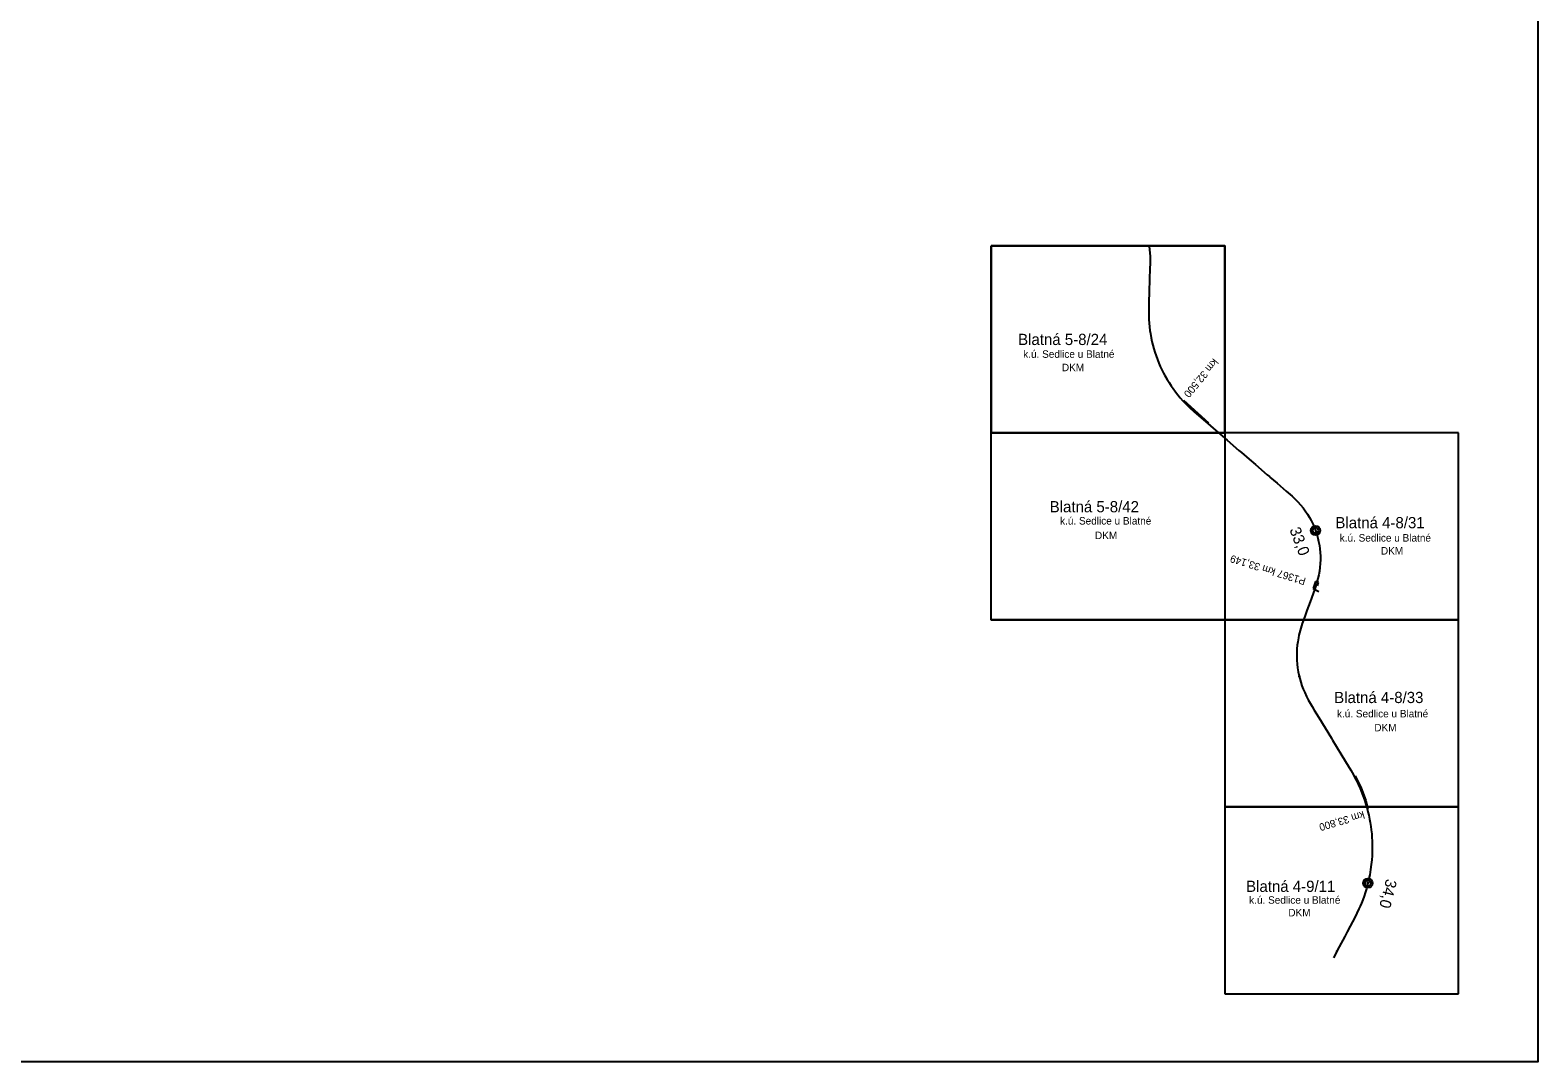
# Model space of a CAD drawing. Extents: x -793522 to -786663, y -1118682 to -1109366.
# Drawn here: x -790694 to -786663, y -1118682 to -1115923 of the extents above; entities that cross this region are included whole.
import ezdxf

# ---------------------------------------------------------------- set-up
doc = ezdxf.new("R2010")
doc.units = 0
doc.layers.add('Vrstva 1', color=7, linetype='Continuous')
doc.layers.add('Vrstva 5', color=7, linetype='Continuous')

msp = doc.modelspace()

# ---------------------------------------------------------------- linework, layer by layer
at = {"layer": 'Vrstva 1'}
for p, q in [((-787500, -1116500), (-788125, -1116500)), ((-788125, -1116500), (-788125, -1117000)), ((-787500, -1117000), (-787500, -1116500)), ((-787610.17, -1116912.47), (-787543.59, -1116973.16)), ((-788125, -1117000), (-787500, -1117000)), ((-786875, -1117000), (-787500, -1117000)), ((-787500, -1117000), (-787500, -1117500)), ((-786875, -1117500), (-786875, -1117000)), ((-787257.92, -1117397.49), (-787263.58, -1117416.4)), ((-787263.58, -1117416.4), (-787248.8, -1117423.73)), ((-787249.76, -1117400.11), (-787257.92, -1117397.49)), ((-787252.28, -1117409.05), (-787249.76, -1117400.11)), ((-788125, -1117500), (-787500, -1117500)), ((-786875, -1117500), (-787500, -1117500)), ((-787500, -1117500), (-787500, -1118000)), ((-787500, -1117500), (-786875, -1117500)), ((-786875, -1118000), (-786875, -1117500)), ((-787151.77, -1117917.42), (-787135.79, -1117950.31)), ((-787135.79, -1117950.31), (-787123.32, -1117983.19)), ((-787123.32, -1117983.19), (-787117.52, -1118004.28)), ((-786875, -1118000), (-787500, -1118000)), ((-787500, -1118000), (-787500, -1118500)), ((-787500, -1118000), (-786875, -1118000)), ((-786875, -1118500), (-786875, -1118000)), ((-787500, -1118500), (-786875, -1118500))]:
    msp.add_line(p, q, dxfattribs=at)
for points in [[(-788125, -1116500), (-787500, -1116500), (-787500, -1117000), (-788125, -1117000)], [(-788125, -1117000), (-787500, -1117000), (-787500, -1117500), (-788125, -1117500)]]:
    msp.add_lwpolyline(points, close=True, dxfattribs=at)
at = {"layer": 'Vrstva 5'}
msp.add_line((-787264.124, -1117429.531), (-787272.215, -1117452.199), dxfattribs=at)
msp.add_lwpolyline([(-793521.92, -1109366.5), (-786663.17, -1109366.5), (-786663.17, -1118682.04), (-793521.92, -1118682.04)], close=True, dxfattribs=at)
for points in [[(-787702.18, -1116501.519), (-787700.372, -1116518.851), (-787699.928, -1116528.643), (-787699.805, -1116538.532), (-787699.903, -1116548.479), (-787700.14, -1116558.804)], [(-787700.14, -1116558.804), (-787701.094, -1116590.796), (-787701.939, -1116620.528), (-787702.796, -1116651.973)], [(-787702.796, -1116651.973), (-787702.839, -1116653.476), (-787703.182, -1116666.814), (-787703.224, -1116669.056), (-787703.262, -1116685.938), (-787702.875, -1116697.001), (-787702.251, -1116706.456), (-787701.319, -1116716.327), (-787700.066, -1116726.364), (-787698.933, -1116733.965), (-787696.768, -1116746.104), (-787694.788, -1116755.499), (-787692.394, -1116765.447), (-787689.88, -1116774.799), (-787687.019, -1116784.337), (-787683.839, -1116793.908), (-787680.302, -1116803.582), (-787676.467, -1116813.13), (-787672.577, -1116822.084), (-787668.102, -1116831.643), (-787663.922, -1116839.942), (-787660.465, -1116846.442), (-787654.268, -1116857.303), (-787649.157, -1116865.615), (-787643.467, -1116874.28), (-787638.382, -1116881.6), (-787631.784, -1116890.547), (-787626.005, -1116897.887), (-787619.293, -1116905.951), (-787612.03, -1116914.141), (-787605.82, -1116920.753), (-787594.635, -1116931.834), (-787581.88, -1116943.427), (-787568.993, -1116954.583)], [(-787568.993, -1116954.583), (-787545.215, -1116975.067), (-787531.212, -1116987.128), (-787493.359, -1117019.729), (-787462.151, -1117046.641), (-787455.433, -1117052.443), (-787434.547, -1117070.453)], [(-787434.547, -1117070.453), (-787417.79, -1117084.905), (-787386.337, -1117112.07), (-787380.687, -1117116.941), (-787379.218, -1117118.208), (-787360.32, -1117134.512), (-787335.866, -1117155.607)], [(-787335.866, -1117155.607), (-787320.244, -1117169.319), (-787311.1, -1117177.883), (-787305.041, -1117183.968)], [(-787305.041, -1117183.968), (-787297.251, -1117192.53), (-787290.607, -1117200.614), (-787284.884, -1117208.27), (-787278.988, -1117216.979), (-787273.485, -1117226.042), (-787269.093, -1117234.068), (-787264.497, -1117243.474), (-787260.627, -1117252.403), (-787257.299, -1117261.108), (-787254.006, -1117271.02), (-787251.155, -1117281.268), (-787249.101, -1117290.263), (-787247.167, -1117300.814), (-787245.916, -1117309.872), (-787244.976, -1117319.945), (-787244.497, -1117329.869), (-787244.472, -1117339.844), (-787244.881, -1117349.453), (-787245.815, -1117359.915), (-787247.114, -1117369.403), (-787249.025, -1117379.864), (-787251.285, -1117389.688)], [(-787251.285, -1117389.688), (-787253.839, -1117398.971), (-787255.092, -1117403.108), (-787257.722, -1117411.266), (-787259.626, -1117416.843), (-787264.124, -1117429.531)], [(-787272.215, -1117452.199), (-787280.557, -1117475.364), (-787286.198, -1117490.977), (-787292.861, -1117509.706)], [(-787292.861, -1117509.706), (-787298.773, -1117528.625), (-787301.815, -1117540.929), (-787303.306, -1117548.175), (-787305.082, -1117558.822), (-787306.246, -1117568.012), (-787307.096, -1117577.718), (-787307.561, -1117587.67), (-787307.605, -1117599.168), (-787307.529, -1117601.826), (-787307.284, -1117607.901), (-787306.437, -1117618.657), (-787305.227, -1117628.663), (-787303.498, -1117639.154), (-787301.836, -1117647.306), (-787299.475, -1117657.058), (-787296.766, -1117666.621), (-787293.658, -1117676.109), (-787290.249, -1117685.268), (-787286.351, -1117694.595), (-787281.343, -1117705.236), (-787276.745, -1117714.024), (-787271.82, -1117722.762), (-787266.305, -1117732.107), (-787260.785, -1117741.263), (-787248.978, -1117760.785), (-787231.984, -1117788.82), (-787215.165, -1117816.515), (-787212.016, -1117821.729), (-787202.567, -1117837.346), (-787187.195, -1117862.716), (-787170.659, -1117890.037), (-787163.422, -1117902.053), (-787156.387, -1117914.217), (-787154.007, -1117918.544), (-787148.709, -1117928.619), (-787143.509, -1117939.269), (-787138.085, -1117951.297), (-787132.456, -1117965.092)], [(-787132.456, -1117965.092), (-787129.18, -1117973.865), (-787125.698, -1117983.976), (-787122.561, -1117993.914), (-787119.454, -1118004.788), (-787117.209, -1118013.485), (-787115.158, -1118022.25), (-787112.934, -1118032.964), (-787111.309, -1118041.879), (-787109.63, -1118052.651), (-787108.462, -1118061.673), (-787107.319, -1118072.544), (-787106.61, -1118081.54), (-787106.057, -1118091.606), (-787105.781, -1118101.445), (-787105.715, -1118108.228), (-787105.931, -1118121.346), (-787106.371, -1118131.07), (-787107.097, -1118141.407), (-787108.412, -1118154.507), (-787110.117, -1118167.31), (-787112.557, -1118181.736), (-787114.619, -1118192.052), (-787116.528, -1118200.536), (-787118.994, -1118210.398), (-787121.554, -1118219.604), (-787124.807, -1118230.222), (-787127.634, -1118238.706), (-787131.105, -1118248.301), (-787134.641, -1118257.321), (-787138.262, -1118265.926), (-787141.344, -1118272.829), (-787147.028, -1118284.81), (-787152.465, -1118295.633), (-787158.804, -1118307.841), (-787164.821, -1118319.205), (-787172.912, -1118334.399), (-787179.515, -1118346.767), (-787194.34, -1118374.51), (-787209.821, -1118403.42)]]:
    msp.add_lwpolyline(points, dxfattribs=at)
for centre, radius in [((-787257.403, -1117260.831), 12.457), ((-787257.403, -1117260.831), 7.519), ((-787300.824, -1117651.488), 0.75), ((-787117.492, -1118204.383), 12.457), ((-787117.492, -1118204.383), 7.519), ((-787117.491, -1118204.388), 1.246), ((-787117.491, -1118204.388), 0.752), ((-787200.403, -1118385.832), 0.75)]:
    msp.add_circle(centre, radius, dxfattribs=at)

# ---------------------------------------------------------------- texts
at = {"layer": 'Vrstva 1'}
for s, height, p in [('Blatná 5-8/24', 30, (-788052.561, -1116765)), ('k.ú. Sedlice u Blatné', 20, (-788038.872, -1116799.21)), ('DKM', 20, (-787935.424, -1116835)), ('Blatná 5-8/42', 30, (-787968.125, -1117212.37)), ('k.ú. Sedlice u Blatné', 20, (-787940.362, -1117245.12)), ('Blatná 4-8/31', 30, (-787204.372, -1117255)), ('DKM', 20, (-787847.028, -1117284.06)), ('k.ú. Sedlice u Blatné', 20, (-787192.732, -1117290.66)), ('DKM', 20, (-787082.644, -1117325.3)), ('Blatná 4-8/33', 30, (-787207.621, -1117722.53)), ('k.ú. Sedlice u Blatné', 20, (-787200.132, -1117760.82)), ('DKM', 20, (-787100.224, -1117798.07)), ('Blatná 4-9/11', 30, (-787443.12, -1118227.52)), ('k.ú. Sedlice u Blatné', 20, (-787434.902, -1118259.16)), ('DKM', 20, (-787330.134, -1118292.9))]:
    msp.add_text(s, height=height, dxfattribs=at).set_placement(p)
for s, rotation, p in [('km 32,500', 230.050083, (-787530.917, -1116799.097)), ('P1367 km 33,149', 162.601831, (-787281.768, -1117388.551)), ('km 33,800', 196.347611, (-787129.839, -1118010.912))]:
    msp.add_text(s, height=20, rotation=rotation, dxfattribs=at).set_placement(p)
at = {"layer": 'Vrstva 5'}
for s, rotation, p in [('33,0', 290.922306, (-787327.724, -1117258.618)), ('34,0', 255.961022, (-787068.453, -1118191.118))]:
    msp.add_text(s, height=30, rotation=rotation, dxfattribs=at).set_placement(p)

doc.saveas('drawing.dxf')
